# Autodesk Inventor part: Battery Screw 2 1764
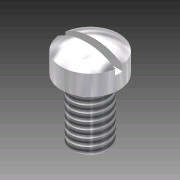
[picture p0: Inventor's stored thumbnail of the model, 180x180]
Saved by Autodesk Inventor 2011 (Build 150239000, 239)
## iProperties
Created: 2008-01
Part Number: Battery Screw 2 1764
Document SubType Name: Modeling
Designer: rlindsay
Density: 1 g/cm^3
Author: rlindsay
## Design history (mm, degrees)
sketch "Sketch1"
  geometry: L1 (-24.313, 21.526)-(-24.313, 6.286); L2 (-29.393, 20.002)-(-29.393, 16.446); L3 (-29.393, 16.446)-(-27.488, 16.446); L4 (-27.488, 16.446)-(-27.488, 6.286); L5 (-27.488, 6.286)-(-24.313, 6.286); A1 r 8.619 centre (-24.497, 12.909) between (-24.313, 21.526) and (-29.393, 20.002)
  constraints: 10 end point, 3 parallel, 2 point on circle, 1 centre point, 1 perpendicular, 1 vertical
  dimensions: "d1" = 15.24 distance of L1.start L1.end; "d2" = 10.16 distance of L3.end L4.end; "d3" = 3.175 distance between parallel lines of L1 L4; "d4" = 5.08 distance between parallel lines of L1 L2; "d6" = 3.556 distance of L2.start L2.end
revolve "Revolution1" sketch "Sketch1" stored, may be unused: angle "d7" = 90 deg
workplane "Work Plane1"
sketch "Sketch2"
  geometry: L1 (6.503, -0.635)-(-6.341, -0.635); L2 (-6.341, -0.635)-(-6.341, 0.635); L3 (-6.341, 0.635)-(6.503, 0.635); L4 (6.503, 0.635)-(6.503, -0.635); C1 r 3.175 at (0, 0) reference
  constraints: 8 end point, 2 parallel, 1 horizontal, 1 perpendicular
  dimensions: "d9" = 1.27 distance between parallel lines of L3 L1; "d10" = 0.635 distance from line of C1.centre L1
extrude "Extrusion1" cut sketch "Sketch2" distance "d11" = 3.81; taper "d12" = 0 deg
thread "Thread1" dims "d13" = 25.4, "d14" = 0
body "Solid1"
other parameters: "d8" = -12.7
